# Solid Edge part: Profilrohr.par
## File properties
Username: ahadarics
Dokumentum tartalom típus: 0
Author: ahadarics
Last saved by: ahadarics
Revision: 77
Sűrűség: 0,000 kg/m^3
Pontosság: 0,990
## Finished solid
Body 1: solid body, 6 faces, 6 edges, 0 vertices.
  Faces by surface: cone 2, cylinder 2, plane 2
  Edges by curve: circle 6
Bounding box of the edges (mm): 26.500 x 26.500 x 58.000, from (-13.25, -13.25, -36.5) to (13.25, 13.25, 21.5).
Cylindrical faces by radius (mm): R12.5 x1, R13.25 x1
Conical faces (half-angle, radius in mm at the cone's reference point): 15 deg R12.567 x2
Planar faces by outward normal: +z 1, -z 1
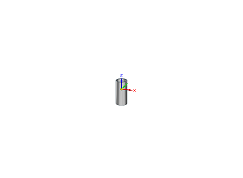
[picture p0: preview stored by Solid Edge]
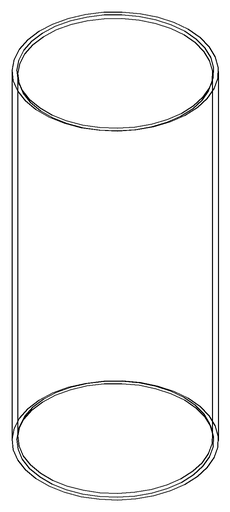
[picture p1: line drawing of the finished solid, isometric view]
